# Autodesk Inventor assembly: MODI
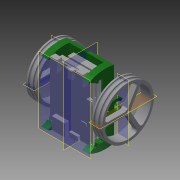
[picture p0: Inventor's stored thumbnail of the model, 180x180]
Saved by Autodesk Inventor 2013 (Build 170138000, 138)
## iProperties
Created: 2013-04
Part Number: MODI
Document SubType Name: Assembly
Designer: otrab
Author: otrab
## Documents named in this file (6)
- C:\Users\otrab\Documents\GitHub\modi\Hardware\inventor 2013\MODI.iam
- C:\Users\otrab\Documents\GitHub\modi\Hardware\inventor 2013\Chasis.ipt
- C:\Users\otrab\Documents\GitHub\modi\Hardware\inventor 2013\bateria.ipt
- C:\Users\otrab\Documents\GitHub\modi\Hardware\inventor 2013\fio.ipt
- C:\Users\otrab\Documents\GitHub\modi\Hardware\inventor 2013\lipoRiderPro.ipt
- C:\Users\otrab\Documents\GitHub\modi\Hardware\inventor 2013\Rueda.ipt
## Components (6 placed, 5 different names)
1. Chasis:1 — Mate:3, Mate:4, Mate:5
2. bateria:1
3. fio:1 — Mate:3, Mate:4
4. lipoRiderPro:1 — Mate:5
5. Rueda:1
6. Rueda:2
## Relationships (3: Mate 3)
- Mate:3: Chasis:1 ↔ fio:1
- Mate:4: Chasis:1 ↔ fio:1
- Mate:5: Chasis:1 ↔ lipoRiderPro:1
